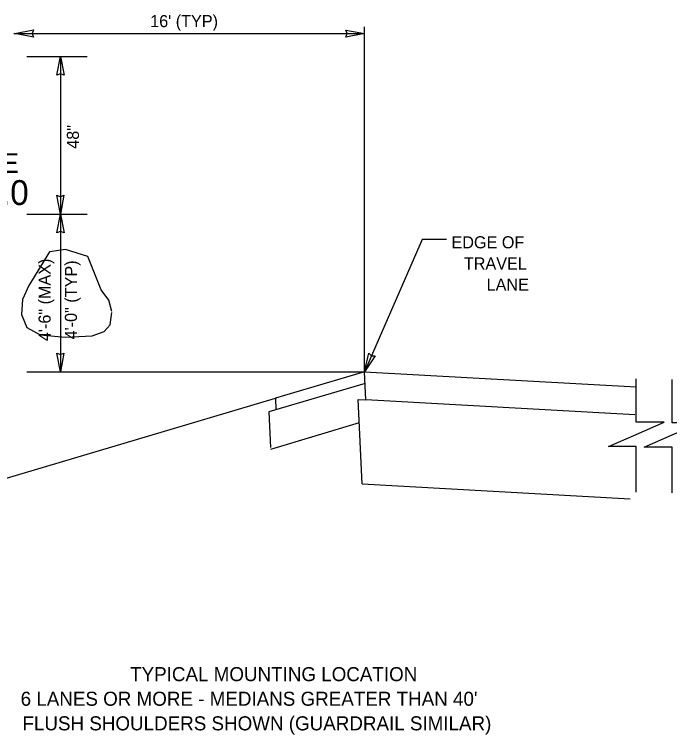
# Model space of a CAD drawing. Extents: x 56768 to 57406, y 11696 to 12105.
# Drawn here: x 57035.7 to 57187.3, y 11742.3 to 11908.9 of the extents above; entities that cross this region are included whole.
import ezdxf

# ---------------------------------------------------------------- set-up
doc = ezdxf.new("R2010")
doc.units = 0
for name, color, linetype in [('52', 7, 'Continuous'), ('62', 7, 'Continuous'), ('Default', 7, 'Continuous'), ('DimLines_dp', 7, 'Continuous'), ('SignPanel', 7, 'Continuous'), ('TextTables', 7, 'Continuous'), ('XSGrdLine_ex', 7, 'Continuous')]:
    doc.layers.add(name, color=color, linetype=linetype)

msp = doc.modelspace()

# ---------------------------------------------------------------- linework, layer by layer
at = {"layer": '52'}
msp.add_line((57038.58, 11826.22), (57116.7, 11826.22), dxfattribs=at)
at = {"layer": '62'}
msp.add_lwpolyline([(57058.24, 11840.16), (57057.54, 11842.76), (57055.73, 11845.17), (57052.63, 11852.92), (57047.53, 11854.52), (57043.83, 11854.02), (57039.03, 11846.17), (57037.53, 11842.96), (57037.33, 11839.46), (57038.53, 11836.46), (57041.63, 11834.75), (57047.53, 11834.25), (57053.63, 11834.55), (57056.43, 11835.56), (57057.84, 11837.06), (57058.24, 11839.96)], dxfattribs=at)
at = {"layer": 'Default'}
for points in [[(57179.58, 11798.37), (57179.58, 11808.93), (57173.12, 11808.93), (57179.58, 11811.74), (57186.04, 11814.56), (57179.58, 11814.56), (57179.58, 11824.56)], [(57187.88, 11798.24), (57187.88, 11808.8), (57181.42, 11808.8), (57187.88, 11811.61), (57194.34, 11814.43), (57187.88, 11814.43), (57187.88, 11824.43)]]:
    msp.add_lwpolyline(points, dxfattribs=at)
at = {"layer": 'DimLines_dp'}
for p, q in [((57116.7, 11826.22), (57116.7, 11906.05)), ((57035.58, 11904.5), (57116.7, 11904.5)), ((57035.77, 11904.5), (57040.12, 11905.34)), ((57040.12, 11903.69), (57035.77, 11904.5)), ((57040.12, 11905.34), (57039.79, 11904.5)), ((57039.79, 11904.5), (57040.12, 11903.69)), ((57112.68, 11904.5), (57112.35, 11905.31)), ((57112.35, 11905.31), (57116.7, 11904.5)), ((57116.7, 11904.5), (57112.35, 11903.66)), ((57112.35, 11903.66), (57112.68, 11904.5)), ((57038.58, 11899.22), (57052.51, 11899.22)), ((57045.51, 11894.87), (57046.32, 11899.22)), ((57046.32, 11899.22), (57046.32, 11862.72)), ((57046.32, 11899.22), (57047.16, 11894.87)), ((57046.32, 11895.2), (57045.51, 11894.87)), ((57047.16, 11894.87), (57046.32, 11895.2)), ((57046.32, 11862.72), (57045.48, 11867.07)), ((57045.48, 11867.07), (57046.32, 11866.74)), ((57046.32, 11862.72), (57045.48, 11867.07)), ((57045.48, 11867.07), (57046.32, 11866.74)), ((57046.32, 11866.74), (57047.13, 11867.07)), ((57047.13, 11867.07), (57046.32, 11862.72)), ((57046.32, 11866.74), (57047.13, 11867.07)), ((57047.13, 11867.07), (57046.32, 11862.72)), ((57038.58, 11862.72), (57052.51, 11862.72)), ((57045.51, 11858.37), (57046.32, 11862.72)), ((57046.32, 11862.72), (57046.32, 11826.22)), ((57046.32, 11862.72), (57047.16, 11858.37)), ((57046.32, 11858.7), (57045.51, 11858.37)), ((57047.16, 11858.37), (57046.32, 11858.7)), ((57130.02, 11856.83), (57116.7, 11826.22)), ((57135.67, 11856.83), (57130.02, 11856.83)), ((57046.32, 11826.22), (57045.48, 11830.57)), ((57045.48, 11830.57), (57046.32, 11830.24)), ((57046.32, 11830.24), (57047.13, 11830.57)), ((57047.13, 11830.57), (57046.32, 11826.22)), ((57116.7, 11826.22), (57117.67, 11830.54)), ((57119.18, 11829.88), (57116.7, 11826.22)), ((57117.67, 11830.54), (57118.31, 11829.9)), ((57118.31, 11829.9), (57119.18, 11829.88))]:
    msp.add_line(p, q, dxfattribs=at)
at = {"layer": 'XSGrdLine_ex'}
for p, q in [((57116.7, 11826.22), (57096.06, 11820.09)), ((57116.99, 11819.71), (57116.7, 11826.22)), ((57116.7, 11826.22), (57179.58, 11822.74)), ((57116.82, 11823.55), (57094.53, 11816.92)), ((57031.1, 11800.77), (57096.06, 11820.09)), ((57096.06, 11820.09), (57096.18, 11817.42)), ((57115.24, 11819.8), (57116.99, 11819.71)), ((57116.11, 11800.26), (57115.24, 11819.8)), ((57179.22, 11816.26), (57116.99, 11819.71)), ((57094.53, 11816.92), (57094.9, 11808.7)), ((57115.48, 11814.4), (57094.91, 11808.28)), ((57116.11, 11800.26), (57178.15, 11796.82))]:
    msp.add_line(p, q, dxfattribs=at)

# ---------------------------------------------------------------- texts
at = {"layer": 'DimLines_dp'}
for s, p in [("16' (TYP)", (57067.09, 11905.97)), ('EDGE OF ', (57136.81, 11854.79)), ('TRAVEL ', (57139.68, 11849.89)), ('LANE', (57144.94, 11844.99))]:
    msp.add_text(s, height=2.8, dxfattribs=at).set_placement(p)
for s, p in [('48"', (57050.61, 11877.83)), ('4\'-6" (MAX)', (57044.06, 11833.32)), ('4\'-0" (TYP)', (57050.15, 11833.72))]:
    msp.add_text(s, height=2.8, rotation=90, dxfattribs=at).set_placement(p)
at = {"layer": 'SignPanel'}
msp.add_text('MILE', height=4.562, dxfattribs=at).set_placement((57022.48, 11872.22))
msp.add_text('XX.0', height=5.75, rotation=360, dxfattribs=at).set_placement((57022.32, 11864.82))
at = {"layer": 'TextTables'}
for s, p in [('TYPICAL MOUNTING LOCATION', (57062.45, 11754.63)), ("6 LANES OR MORE - MEDIANS GREATER THAN 40'", (57037.12, 11748.94)), ('FLUSH SHOULDERS SHOWN (GUARDRAIL SIMILAR)', (57037.54, 11743.25))]:
    msp.add_text(s, height=3.2524, dxfattribs=at).set_placement(p)

doc.saveas('drawing.dxf')
